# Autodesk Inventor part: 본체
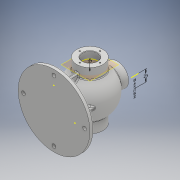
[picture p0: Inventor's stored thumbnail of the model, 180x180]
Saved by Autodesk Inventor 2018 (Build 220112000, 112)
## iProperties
Created: 2020-08
Part Number: 본체
Material: 일반
Document SubType Name: Modeling
Designer: home
Density: 1 g/cm^3
Appearance: 기본값
Author: home
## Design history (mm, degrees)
sketch "스케치1"
  geometry: C1 r 85 at (0, 0); 1 further point
  constraints: 1 centre point, 1 coincident
  dimensions: "d0" = 170 diameter of C1
extrude "돌출1" new body sketch "스케치1" distance "d1" = 10; taper "d2" = 0 deg
sketch "스케치2"
  geometry: L1 (85, 150)-(85, -150); L2 (0, 85)-(0, -85) reference; L3 (116, -42.988)-(116, -68); L4 (116, -68)-(102.5, -68); L5 (102.5, -68)-(102.5, -39.278); L6 (116, 42.988)-(116, 68); L7 (116, 68)-(102.5, 68); L8 (102.5, 68)-(102.5, 39.278); A1 r 43 centre (85, 0) between (102.5, -39.278) and (102.5, 39.278); A2 r 53 centre (85, 0) between (116, -42.988) and (116, 42.988); 2 further points
  constraints: 14 end point, 4 perpendicular, 4 point on circle, 3 vertical, 2 centre point, 2 midpoint, 1 coincident, 1 horizontal alignment
  dimensions: "d3" = 85 distance between parallel lines of L2 L1; "d5" = 43 radius of A1; "d6" = 35 diameter of L5 L1; "d7" = 62 diameter of L3 L1; "d8" = 68 distance from line of L4 A2.centre; "d9" = 68 distance from line of A2.centre L7; "d10" = 62 diameter of L6 L1; "d11" = 35 diameter of L8 L1; "d12" = 53 radius of A2; "d13" = 150 vertical distance of point (0, 0) L1.start; "d14" = 150 distance of L1.end A2.centre
revolve "회전1" sketch "스케치2" stored, may be unused: angle "d15" = 90 deg
node "작업 평면1"
sketch "스케치3"
  geometry: C1 r 27 at (0, 0); 1 further point
  constraints: 1 centre point, 1 coincident
  dimensions: "d17" = 54 diameter of C1
extrude "돌출2" join sketch "스케치3" stored distance "d18" = 10; taper "d19" = 0 deg
sketch "스케치4"
  geometry: C1 r 13 at (0, 0); 1 further point
  constraints: 1 centre point, 1 coincident
  dimensions: "d20" = 26 diameter of C1
extrude "돌출3" cut sketch "스케치4" stored distance "d21" = 10; taper "d22" = 0 deg
sketch "스케치6"
  geometry: L1 (-1, 52)-(1, 52); L2 (4, 49)-(4, -49); L3 (1, -52)-(-1, -52); L4 (-4, -49)-(-4, 49); L5 (-40, 4)-(40, 4); L6 (43, 1)-(43, -1); L7 (40, -4)-(-40, -4); L8 (-43, -1)-(-43, 1); A1 r 3 centre (-40, -1) between (-43, -1) and (-40, -4); A2 r 3 centre (-40, 1) between (-40, 4) and (-43, 1); A3 r 3 centre (40, -1) between (40, -4) and (43, -1); A4 r 3 centre (40, 1) between (43, 1) and (40, 4); A5 r 3 centre (1, -49) between (1, -52) and (4, -49); A6 r 3 centre (-1, -49) between (-4, -49) and (-1, -52); A7 r 3 centre (-1, 49) between (-1, 52) and (-4, 49); A8 r 3 centre (1, 49) between (4, 49) and (1, 52); 1 further point
  constraints: 16 end point, 16 point on circle, 16 tangent, 8 centre point, 7 equal radius, 4 parallel, 2 horizontal, 2 perpendicular
  dimensions: "d29" = 4 distance from line of L5 point (0, 0); "d30" = 4 distance from line of L7 point (0, 0); "d31" = 4 distance from line of L2 point (0, 0); "d32" = 4 distance from line of point (0, 0) L4; "d33" = 104 distance between parallel lines of L1 L3; "d34" = 52 distance from line of L3 point (0, 0); "d35" = 86 distance between parallel lines of L6 L8; "d36" = 43 distance from line of point (0, 0) L8; "d37" = 3 radius of A1
extrude "돌출5" join sketch "스케치6" stored distance "d38" = 8; taper "d39" = 0 deg
sketch "스케치7"
  geometry: C1 r 17.5 at (0, 0) reference; 2 further points
  constraints: 1 vertical alignment
  dimensions: "d40" = 24 distance of C1.centre point (0, 24)
hole "구멍1" sketch "스케치7" at (0, 24) diameter "d41" = 3.242; stored, may be unused: countersink angle "d45" = 90 deg, drill point angle "d47" = 118 deg; dims "d42" = 12, "d43" = 4, "d44" = 2, "d46" = 15
sketch "스케치8"
  geometry: 2 further points
  constraints: 1 horizontal alignment
  dimensions: "d51" = 20 distance of point (-20, 0) point (0, 0)
hole "구멍2" sketch "스케치8" at (-20, 0) diameter "d52" = 3.242; stored, may be unused: countersink angle "d56" = 90 deg, drill point angle "d58" = 118 deg; dims "d53" = 12, "d54" = 4, "d55" = 2, "d57" = 15
node "작업 평면2"
sketch "스케치9"
  geometry: C1 r 17.5 at (0, 0) reference; C2 r 18.5 at (0, 0); 1 further point
  constraints: 1 centre point, 1 coincident
  dimensions: "d63" = 37 diameter of C2
chamfer "모따기1" distance "d64" = 1; stored, may be unused: second distance "d65" = 2, angle "d66" = 45 deg
fillet "모깎기1" dims "d67" = 3
sketch "스케치10"
  geometry: C1 r 4.5 at (0, -72.5); 1 further point
  constraints: 1 centre point, 1 vertical alignment
  dimensions: "d69" = 9 diameter of C1; "d70" = 72.5 distance of point (0, 0) C1.centre
extrude "돌출6" cut sketch "스케치10" extent not by distance; stored distance "d71" = 1.75; taper "d72" = 0 deg
node "작업 평면3"
sketch "스케치11"
  geometry: L1 (150, 27)-(132.286, 27) reference; 2 further points
  constraints: 1 other
  dimensions: "d78" = 27 distance from line of L1 point (141, 0)
node "솔리드1"
pattern_circular "원형 패턴1" dims angle "d49" = 360 deg
mirror "미러1"
pattern_circular "원형 패턴2" dims angle "d60" = 360 deg
pattern_circular "원형 패턴3" dims angle "d74" = 360 deg
other parameters: "d4" = 53, "d62" = -16
